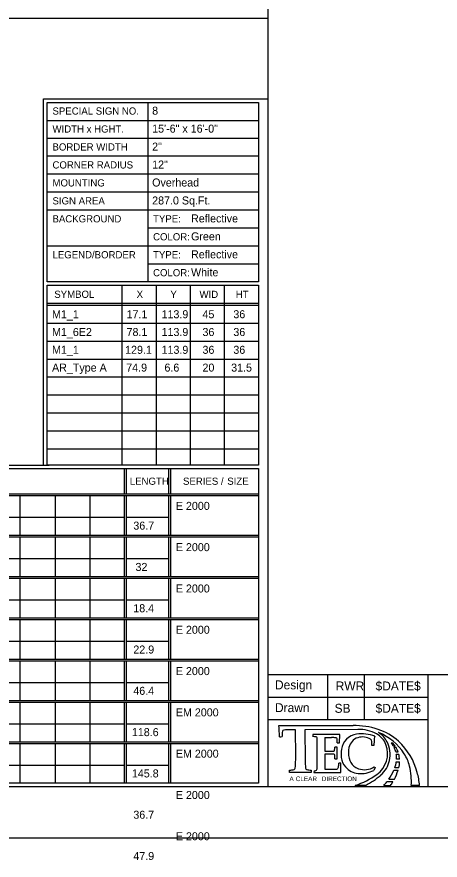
# Model space of a CAD drawing. Extents: x 2149934 to 2150188, y 145113 to 145238.
# Drawn here: x 2150119.2 to 2150146.6, y 145112.6 to 145167.1 of the extents above; entities that cross this region are included whole.
import ezdxf

# ---------------------------------------------------------------- set-up
doc = ezdxf.new("R2010")
doc.units = 0
for name, color, linetype in [('BORDER', 7, 'Continuous'), ('DATE', 7, 'Continuous'), ('GSSHT', 7, 'Continuous'), ('Level 1', 7, 'Continuous'), ('PDF', 7, 'Continuous'), ('TEC LOGO', 7, 'Continuous')]:
    doc.layers.add(name, color=color, linetype=linetype)

msp = doc.modelspace()

# ---------------------------------------------------------------- linework, layer by layer
at = {"layer": 'BORDER'}
for p, q in [((2150171.536, 145124.606), (2150135.447, 145124.606)), ((2150135.447, 145124.606), (2150135.447, 145117.388)), ((2150139.297, 145124.606), (2150139.297, 145121.719)), ((2150141.703, 145121.719), (2150141.703, 145124.606)), ((2150145.8, 145117.359), (2150145.8, 145124.577)), ((2150135.447, 145123.162), (2150145.8, 145123.162)), ((2150135.447, 145121.719), (2150145.8, 145121.719)), ((2150017.557, 145117.388), (2150171.536, 145117.388)), ((2150010.458, 145114.088), (2150174.061, 145114.088))]:
    msp.add_line(p, q, dxfattribs=at)
at = {"layer": 'Level 1'}
for p, q in [((2150135.447, 145216.512), (2150135.447, 145124.606)), ((2150135.447, 145166.95), (2150017.557, 145166.95)), ((2150120.969, 145161.778), (2150135.447, 145161.778)), ((2150127.694, 145161.546), (2150127.694, 145149.975)), ((2150121.201, 145160.387), (2150134.843, 145160.387)), ((2150121.201, 145159.227), (2150134.843, 145159.227)), ((2150121.201, 145158.091), (2150134.843, 145158.091)), ((2150121.201, 145156.932), (2150134.843, 145156.932)), ((2150121.201, 145155.772), (2150134.843, 145155.772)), ((2150121.201, 145154.613), (2150134.843, 145154.613)), ((2150127.694, 145153.453), (2150134.843, 145153.453)), ((2150121.201, 145152.294), (2150134.843, 145152.294)), ((2150127.694, 145151.134), (2150134.843, 145151.134)), ((2150121.201, 145138.143), (2150121.201, 145149.743)), ((2150121.201, 145149.743), (2150134.843, 145149.743)), ((2150126.031, 145149.737), (2150126.031, 145148.578)), ((2150128.234, 145149.737), (2150128.234, 145148.578)), ((2150130.437, 145149.737), (2150130.437, 145148.578)), ((2150132.64, 145149.737), (2150132.64, 145148.578)), ((2150134.843, 145149.743), (2150134.843, 145138.143)), ((2150121.201, 145148.578), (2150134.843, 145148.578)), ((2150121.201, 145148.462), (2150134.843, 145148.462)), ((2150126.031, 145148.578), (2150126.031, 145138.143)), ((2150128.234, 145148.578), (2150128.234, 145138.143)), ((2150130.437, 145148.578), (2150130.437, 145138.143)), ((2150132.64, 145148.578), (2150132.64, 145138.143)), ((2150121.201, 145147.303), (2150134.843, 145147.303)), ((2150121.201, 145146.143), (2150134.843, 145146.143)), ((2150121.201, 145144.984), (2150134.843, 145144.984)), ((2150121.201, 145143.824), (2150134.843, 145143.824)), ((2150121.201, 145142.665), (2150134.843, 145142.665)), ((2150121.201, 145141.505), (2150134.843, 145141.505)), ((2150121.201, 145140.346), (2150134.843, 145140.346)), ((2150121.201, 145139.186), (2150134.843, 145139.186)), ((2150076.316, 145138.143), (2150121.342, 145138.143)), ((2150134.843, 145138.143), (2150121.201, 145138.143)), ((2150126.185, 145137.911), (2150126.185, 145136.288)), ((2150126.301, 145137.911), (2150126.301, 145136.288)), ((2150129.048, 145137.911), (2150129.048, 145136.288)), ((2150129.164, 145137.911), (2150129.164, 145136.288)), ((2150076.548, 145136.288), (2150134.843, 145136.288)), ((2150076.548, 145136.172), (2150134.843, 145136.172)), ((2150119.449, 145136.172), (2150119.449, 145133.621)), ((2150121.721, 145136.172), (2150121.721, 145133.621)), ((2150123.97, 145136.172), (2150123.97, 145133.621)), ((2150126.185, 145136.172), (2150126.185, 145133.621)), ((2150126.301, 145136.172), (2150126.301, 145133.621)), ((2150129.048, 145136.172), (2150129.048, 145133.621)), ((2150129.164, 145136.172), (2150129.164, 145133.621)), ((2150076.548, 145134.78), (2150126.185, 145134.78)), ((2150126.301, 145134.78), (2150129.048, 145134.78)), ((2150076.548, 145133.621), (2150134.843, 145133.621)), ((2150076.548, 145133.505), (2150134.843, 145133.505)), ((2150119.449, 145133.505), (2150119.449, 145130.954)), ((2150121.721, 145133.505), (2150121.721, 145130.954)), ((2150123.97, 145133.505), (2150123.97, 145130.954)), ((2150126.185, 145133.505), (2150126.185, 145130.954)), ((2150126.301, 145133.505), (2150126.301, 145130.954)), ((2150129.048, 145133.505), (2150129.048, 145130.954)), ((2150129.164, 145133.505), (2150129.164, 145130.954)), ((2150076.548, 145132.113), (2150126.185, 145132.113)), ((2150126.301, 145132.113), (2150129.048, 145132.113)), ((2150076.548, 145130.954), (2150134.843, 145130.954)), ((2150076.548, 145130.838), (2150134.843, 145130.838)), ((2150119.449, 145130.838), (2150119.449, 145128.287)), ((2150121.721, 145130.838), (2150121.721, 145128.287)), ((2150123.97, 145130.838), (2150123.97, 145128.287)), ((2150126.185, 145130.838), (2150126.185, 145128.287)), ((2150126.301, 145130.838), (2150126.301, 145128.287)), ((2150129.048, 145130.838), (2150129.048, 145128.287)), ((2150129.164, 145130.838), (2150129.164, 145128.287)), ((2150076.548, 145129.447), (2150126.185, 145129.447)), ((2150126.301, 145129.447), (2150129.048, 145129.447)), ((2150076.548, 145128.287), (2150134.843, 145128.287)), ((2150076.548, 145128.171), (2150134.843, 145128.171)), ((2150119.449, 145128.171), (2150119.449, 145125.62)), ((2150121.721, 145128.171), (2150121.721, 145125.62)), ((2150123.97, 145128.171), (2150123.97, 145125.62)), ((2150126.185, 145128.171), (2150126.185, 145125.62)), ((2150126.301, 145128.171), (2150126.301, 145125.62)), ((2150129.048, 145128.171), (2150129.048, 145125.62)), ((2150129.164, 145128.171), (2150129.164, 145125.62)), ((2150076.548, 145126.78), (2150126.185, 145126.78)), ((2150126.301, 145126.78), (2150129.048, 145126.78)), ((2150076.548, 145125.62), (2150134.843, 145125.62)), ((2150076.548, 145125.504), (2150134.843, 145125.504)), ((2150119.449, 145125.504), (2150119.449, 145122.954)), ((2150121.721, 145125.504), (2150121.721, 145122.954)), ((2150123.97, 145125.504), (2150123.97, 145122.954)), ((2150126.185, 145125.504), (2150126.185, 145122.954)), ((2150126.301, 145125.504), (2150126.301, 145122.954)), ((2150129.048, 145125.504), (2150129.048, 145122.954)), ((2150129.164, 145125.504), (2150129.164, 145122.954)), ((2150076.548, 145124.113), (2150126.185, 145124.113)), ((2150126.301, 145124.113), (2150129.048, 145124.113)), ((2150076.548, 145122.954), (2150134.843, 145122.954)), ((2150076.548, 145122.838), (2150134.843, 145122.838)), ((2150119.449, 145122.838), (2150119.449, 145120.287)), ((2150121.721, 145122.838), (2150121.721, 145120.287)), ((2150123.97, 145122.838), (2150123.97, 145120.287)), ((2150126.185, 145122.838), (2150126.185, 145120.287)), ((2150126.301, 145122.838), (2150126.301, 145120.287)), ((2150129.048, 145122.838), (2150129.048, 145120.287)), ((2150129.164, 145122.838), (2150129.164, 145120.287)), ((2150076.548, 145121.446), (2150126.185, 145121.446)), ((2150126.301, 145121.446), (2150129.048, 145121.446)), ((2150076.548, 145120.287), (2150134.843, 145120.287)), ((2150076.548, 145120.171), (2150134.843, 145120.171)), ((2150119.449, 145120.171), (2150119.449, 145117.62)), ((2150121.721, 145120.171), (2150121.721, 145117.62)), ((2150123.97, 145120.171), (2150123.97, 145117.62)), ((2150126.185, 145120.171), (2150126.185, 145117.62)), ((2150126.301, 145120.171), (2150126.301, 145117.62)), ((2150129.048, 145120.171), (2150129.048, 145117.62)), ((2150129.164, 145120.171), (2150129.164, 145117.62)), ((2150076.548, 145118.779), (2150126.185, 145118.779)), ((2150126.301, 145118.779), (2150129.048, 145118.779))]:
    msp.add_line(p, q, dxfattribs=at)
msp.add_lwpolyline([(2150120.969, 145138.143), (2150120.969, 145161.778)], dxfattribs=at)
for points in [[(2150121.201, 145161.546), (2150134.843, 145161.546), (2150134.843, 145149.975), (2150121.201, 145149.975)], [(2150076.548, 145137.911), (2150134.843, 145137.911), (2150134.843, 145117.62), (2150076.548, 145117.62)]]:
    msp.add_lwpolyline(points, close=True, dxfattribs=at)
at = {"layer": 'PDF'}
msp.add_lwpolyline([(2150010.458, 145114.088), (2150174.061, 145114.088), (2150174.061, 145219.948), (2150010.458, 145219.948)], close=True, dxfattribs=at)
at = {"layer": 'TEC LOGO'}
for p, q in [((2150136.163, 145121.335), (2150140.955, 145121.335)), ((2150137.238, 145121.058), (2150136.905, 145121.056)), ((2150141.264, 145121.082), (2150137.847, 145121.062)), ((2150137.847, 145121.062), (2150137.86, 145119.111)), ((2150138.352, 145120.759), (2150138.349, 145120.611)), ((2150140.106, 145120.759), (2150138.352, 145120.759)), ((2150139.134, 145120.555), (2150139.56, 145120.552)), ((2150140.07, 145120.219), (2150140.106, 145120.759)), ((2150139.925, 145119.934), (2150139.778, 145119.934)), ((2150139.925, 145120.219), (2150140.07, 145120.219)), ((2150139.925, 145119.172), (2150139.925, 145119.934)), ((2150142.3, 145120.043), (2150142.168, 145120.048)), ((2150142.307, 145120.354), (2150142.3, 145120.043)), ((2150143.414, 145120.213), (2150143.504, 145120.213)), ((2150143.669, 145120.008), (2150143.554, 145120.008)), ((2150143.731, 145119.909), (2150143.606, 145119.909)), ((2150143.709, 145119.627), (2150143.862, 145119.627)), ((2150143.74, 145119.471), (2150143.909, 145119.471)), ((2150139.785, 145119.172), (2150139.925, 145119.172)), ((2150140.175, 145118.91), (2150140.043, 145118.91)), ((2150140.159, 145118.3), (2150140.175, 145118.91)), ((2150143.743, 145118.997), (2150143.958, 145118.997)), ((2150143.957, 145119.151), (2150143.755, 145119.151)), ((2150136.856, 145118.3), (2150136.856, 145118.452)), ((2150138.255, 145118.3), (2150136.856, 145118.3)), ((2150138.255, 145118.452), (2150138.255, 145118.3)), ((2150138.439, 145118.399), (2150138.43, 145118.3)), ((2150138.43, 145118.3), (2150140.159, 145118.3)), ((2150142.374, 145118.62), (2150142.288, 145118.435)), ((2150142.324, 145118.657), (2150142.374, 145118.62)), ((2150143.86, 145118.438), (2150143.591, 145118.438)), ((2150143.903, 145118.595), (2150143.65, 145118.595)), ((2150143.52, 145117.689), (2150143.126, 145117.689)), ((2150143.264, 145117.867), (2150143.623, 145117.867)), ((2150141.747, 145117.467), (2150141.099, 145117.467)), ((2150142.942, 145117.467), (2150143.375, 145117.467)), ((2150145.252, 145117.467), (2150144.714, 145117.467))]:
    msp.add_line(p, q, dxfattribs=at)
for centre, radius, start, end in [((2150129.713, 145120.639), 6.487, 359.663, 6.1563), ((2150137.218, 145120.781), 0.843, 167.5337, 178.5623), ((2150136.49, 145120.942), 0.0962, 94.698, 167.5337), ((2150136.937, 145115.493), 5.563, 90.3367, 94.698), ((2150046.46, 145119.478), 90.791, 359.77628, 0.99712), ((2150140.955, 145116.038), 5.297, 72.2522, 90), ((2150141.28, 145118.51), 2.573, 62.4303, 90.3367), ((2150141.492, 145117.716), 3.535, 47.2839, 72.2522), ((2150136.235, 145120.976), 0.377, 264.6321, 291.5899), ((2150142.861, 145120.639), 6.487, 178.5623, 180.1181), ((2150138.383, 145119.475), 1.137, 80.6874, 91.7186), ((2150138.555, 145120.525), 0.0722, 1.4011, 80.6874), ((2150097.794, 145119.528), 40.845, 358.5952, 1.4011), ((2150222.857, 145119.533), 83.729, 179.30064, 179.90313), ((2150139.538, 145117.558), 2.995, 83.8831, 89.5816), ((2150139.849, 145120.463), 0.0722, 5.4112, 83.8831), ((2150138.327, 145120.319), 1.601, 356.4205, 5.4112), ((2150141.338, 145119.635), 1.149, 97.9231, 172.0344), ((2150141.512, 145119.746), 0.839, 107.7088, 167.9528), ((2150141.514, 145118.371), 2.426, 69.3982, 97.9231), ((2150141.562, 145119.589), 1.004, 58.2676, 107.7088), ((2150141.997, 145120.293), 0.176, 2.4202, 58.2676), ((2150143.117, 145120.335), 0.81, 157.7575, 178.6366), ((2150141.873, 145119.647), 1.289, 20.6867, 62.4303), ((2150141.269, 145117.57), 3.562, 32.9982, 68.0651), ((2150141.873, 145119.647), 1.426, 26.3065, 59.3722), ((2150138.932, 145119.89), 0.847, 349.9583, 3.0005), ((2150142.25, 145119.588), 1.594, 167.9528, 193.0838), ((2150140.098, 145120.213), 2.077, 355.4457, 2.4202), ((2150141.537, 145119.52), 1.649, 305.1645, 20.6867), ((2150141.484, 145119.455), 1.86, 348.2376, 26.3065), ((2150142.22, 145119.245), 1.536, 29.7365, 39.0219), ((2150142.29, 145119.068), 1.669, 34.2695, 43.3207), ((2150142.22, 145119.245), 1.536, 14.3628, 25.5725), ((2150142.29, 145119.068), 1.669, 19.5618, 30.2542), ((2150141.052, 145117.24), 4.183, 14.7043, 47.2839), ((2150139.363, 145128.515), 8.844, 268.4788, 271.5206), ((2150139.362, 145110.642), 8.844, 88.4794, 91.5212), ((2150222.857, 145119.533), 83.729, 180.03409, 180.69936), ((2150139.572, 145120.641), 0.967, 271.5206, 277.9096), ((2150139.571, 145118.517), 0.967, 81.2846, 88.4794), ((2150139.695, 145119.755), 0.0722, 277.9096, 349.9583), ((2150139.707, 145119.401), 0.0722, 5.6885, 81.2846), ((2150138.141, 145119.245), 1.646, 357.4607, 5.6885), ((2150142.345, 145119.494), 2.166, 172.0344, 186.3105), ((2150142.22, 145119.245), 1.536, 2.0409, 8.4283), ((2150141.804, 145119.231), 1.952, 357.6694, 2.0409), ((2150142.29, 145119.068), 1.669, 2.8667, 13.9687), ((2150142.146, 145118.139), 2.517, 12.951, 32.9982), ((2150132.45, 145119.143), 4.801, 353.2347, 359.7763), ((2150142.661, 145119.143), 4.801, 180.3775, 186.7653), ((2150139.168, 145118.894), 0.876, 342.6077, 1.0782), ((2150141.269, 145119.375), 1.083, 186.3105, 221.5776), ((2150141.645, 145119.448), 0.973, 193.0838, 228.7889), ((2150141.651, 145119.42), 1.689, 310.5997, 348.2376), ((2150141.804, 145119.231), 1.952, 341.0487, 353.1199), ((2150142.049, 145119.055), 1.911, 346.0491, 358.2376), ((2150142.049, 145119.055), 1.911, 2.8951, 2.9107), ((2150136.867, 145119.381), 0.929, 269.3409, 287.8364), ((2150137.122, 145118.588), 0.0962, 287.8364, 353.2347), ((2150137.989, 145118.588), 0.0962, 186.7653, 252.1636), ((2150138.244, 145119.381), 0.929, 252.1636, 270.6591), ((2150138.412, 145118.712), 0.314, 274.8598, 303.0633), ((2150138.531, 145118.529), 0.0962, 303.0633, 358.5952), ((2150139.369, 145127.352), 8.844, 268.4788, 273.4332), ((2150139.893, 145118.62), 0.0962, 273.4332, 326.9687), ((2150139.753, 145118.711), 0.263, 326.9687, 342.6077), ((2150141.404, 145119.495), 1.263, 221.5776, 264.5103), ((2150141.577, 145119.37), 0.87, 228.7889, 251.3711), ((2150141.454, 145120.022), 1.792, 264.5103, 297.7193), ((2150141.691, 145119.707), 1.226, 251.3711, 301.0817), ((2150141.152, 145119.455), 2.643, 323.1081, 337.382), ((2150140.843, 145119.355), 3.152, 331.8459, 343.1036), ((2150141.152, 145119.455), 2.643, 341.0109, 341.0487), ((2150140.843, 145119.355), 3.152, 346.0548, 346.0603), ((2150140.037, 145117.654), 4.681, 357.7052, 12.951), ((2150139.621, 145116.864), 5.663, 6.1104, 14.7043), ((2150139.346, 145122.63), 5.453, 288.7522, 305.1645), ((2150139.464, 145121.971), 5.05, 296.8707, 310.5997), ((2150137.249, 145122.384), 7.522, 319.179, 321.3834), ((2150137.249, 145122.384), 7.522, 323.0973, 323.1081), ((2150137.725, 145121.305), 6.831, 325.8118, 328.04), ((2150140.843, 145119.355), 3.152, 327.9791, 328.0787)]:
    msp.add_arc(centre, radius, start, end, dxfattribs=at)

# ---------------------------------------------------------------- texts
at = {"layer": 'BORDER'}
for s, p in [('Design', (2150135.913, 145123.665)), ('RWR', (2150139.833, 145123.596)), ('Drawn', (2150135.913, 145122.195)), ('SB ', (2150139.76, 145122.152))]:
    msp.add_text(s, height=0.5774, dxfattribs=at).set_placement(p)
at = {"layer": 'DATE'}
for p in [(2150142.406, 145123.595), (2150142.406, 145122.152)]:
    msp.add_text('$DATE$', height=0.5774, dxfattribs=at).set_placement(p)
at = {"layer": 'GSSHT'}
for s, height, p in [('8', 0.517, (2150127.983, 145160.753)), ('Overhead', 0.5165, (2150127.983, 145156.117))]:
    msp.add_text(s, height=height, dxfattribs=at).set_placement(p)
at = {"layer": 'Level 1'}
for s, height, p in [('SPECIAL SIGN NO.', 0.46374, (2150121.549, 145160.758)), ('15\'-6" x 16\'-0"', 0.51652, (2150127.983, 145159.594)), ('WIDTH x HGHT.', 0.46374, (2150121.549, 145159.598)), ('BORDER WIDTH', 0.46374, (2150121.549, 145158.439)), ('2"', 0.5165, (2150127.983, 145158.435)), ('CORNER RADIUS', 0.46374, (2150121.549, 145157.28)), ('12"', 0.5165, (2150127.983, 145157.276)), ('MOUNTING', 0.4637, (2150121.549, 145156.12)), ('SIGN AREA', 0.4638, (2150121.549, 145154.961)), ('287.0 Sq.Ft.', 0.51652, (2150127.983, 145154.958)), ('BACKGROUND', 0.4637, (2150121.549, 145153.801)), ('TYPE:', 0.4637, (2150128.042, 145153.801)), ('Reflective', 0.5165, (2150130.494, 145153.8)), ('COLOR:', 0.4637, (2150128.042, 145152.642)), ('Green', 0.5165, (2150130.494, 145152.641)), ('LEGEND/BORDER', 0.46374, (2150121.549, 145151.482)), ('Reflective', 0.5165, (2150130.494, 145151.482)), ('TYPE:', 0.4637, (2150128.042, 145151.482)), ('White', 0.5165, (2150130.494, 145150.323)), ('COLOR:', 0.4637, (2150128.042, 145150.323)), ('SYMBOL', 0.4637, (2150121.665, 145148.931)), ('X', 0.464, (2150126.981, 145148.926)), ('Y', 0.464, (2150129.161, 145148.926)), ('WID', 0.4637, (2150131.04, 145148.926)), ('HT', 0.4637, (2150133.382, 145148.926)), ('113.9', 0.5165, (2150128.589, 145147.616)), ('36', 0.5165, (2150133.225, 145147.616)), ('M1_1', 0.5165, (2150121.52, 145147.616)), ('17.1', 0.5165, (2150126.331, 145147.616)), ('45', 0.5165, (2150131.233, 145147.616)), ('M1_6E2', 0.5165, (2150121.52, 145146.468)), ('78.1', 0.5165, (2150126.331, 145146.468)), ('113.9', 0.5165, (2150128.589, 145146.468)), ('36', 0.5165, (2150131.233, 145146.468)), ('36', 0.5165, (2150133.225, 145146.468)), ('M1_1', 0.5165, (2150121.52, 145145.32)), ('129.1', 0.5165, (2150126.237, 145145.32)), ('113.9', 0.5165, (2150128.589, 145145.32)), ('36', 0.5165, (2150131.233, 145145.32)), ('36', 0.5165, (2150133.225, 145145.32)), ('AR_Type A', 0.5165, (2150121.52, 145144.172)), ('74.9', 0.5165, (2150126.31, 145144.172)), ('6.6', 0.5165, (2150128.777, 145144.172)), ('20', 0.5165, (2150131.233, 145144.172)), ('31.5', 0.5165, (2150133.084, 145144.172)), ('LENGTH', 0.4638, (2150126.541, 145136.867)), ('LENGTH', 0.4638, (2150126.541, 145136.867)), ('SERIES /', 0.4638, (2150129.975, 145136.867)), ('SIZE', 0.4638, (2150132.832, 145136.867)), ('E 2000', 0.5165, (2150129.512, 145135.248)), ('36.7', 0.5165, (2150126.768, 145133.973)), ('E 2000', 0.5165, (2150129.512, 145132.583)), ('32', 0.5165, (2150126.909, 145131.308)), ('E 2000', 0.5165, (2150129.512, 145129.917)), ('18.4', 0.5165, (2150126.766, 145128.643)), ('E 2000', 0.5165, (2150129.512, 145127.252)), ('22.9', 0.5165, (2150126.768, 145125.977)), ('E 2000', 0.5165, (2150129.512, 145124.586)), ('46.4', 0.5165, (2150126.766, 145123.312)), ('EM 2000', 0.5165, (2150129.512, 145121.921)), ('118.6', 0.5165, (2150126.674, 145120.646)), ('EM 2000', 0.5165, (2150129.512, 145119.256)), ('145.8', 0.5165, (2150126.674, 145117.981)), ('E 2000', 0.5165, (2150129.512, 145116.59)), ('36.7', 0.5165, (2150126.768, 145115.315)), ('E 2000', 0.5165, (2150129.512, 145113.925)), ('47.9', 0.5165, (2150126.768, 145112.65))]:
    msp.add_text(s, height=height, dxfattribs=at).set_placement(p)
at = {"layer": 'TEC LOGO'}
for s, height, p in [('A', 0.298, (2150136.847, 145117.742)), ('CLEAR', 0.2983, (2150137.254, 145117.742)), ('DIRECTION', 0.2983, (2150138.933, 145117.742))]:
    msp.add_text(s, height=height, dxfattribs=at).set_placement(p)

doc.saveas('drawing.dxf')
